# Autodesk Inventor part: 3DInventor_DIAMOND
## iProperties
Created: 2006-11
Part Number: 3DInventor_DIAMOND
Document SubType Name: Modeling
Designer: conardl1
Density: 1 g/cm^3
Translation Standard: STEP AP203
File Name: DIAMOND
Preprocessor: PRO/ENGINEER BY PARAMETRIC TECHNOLOGY CORPORATION, 2004280
Postprocessor: Build: 211m, Release: 10 - Date: Fri 03/18/2005
Sent Units: MILLIMETERS
Uncertainty: 0.003970987084496
DESCRIPTION: Arrow Control Pad
MODELED_BY: L Conard
Author: conardl1
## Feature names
1. Base1
